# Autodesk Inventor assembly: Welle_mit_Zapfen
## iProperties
Shininess: 64.0
Length Units: 11269
Angle Units: 11279
Time Units: 11290
Mass Units: 11283
Length Display Precision: 3
Angle Display Precision: 2
Compacted: True
Created: 2004-05
Part Number: Welle_mit_Zapfen
Document SubType Name: Assembly
Designer: KWU_CAD
Manufacturer: Standard
Standards Organization: Custom
Density: 0.0
Volumn: 0.0
Area: 0.0
PropertySet Name: Model Information
Control State: 0
Master: False
Checked Out: False
Author: KWU_CAD
